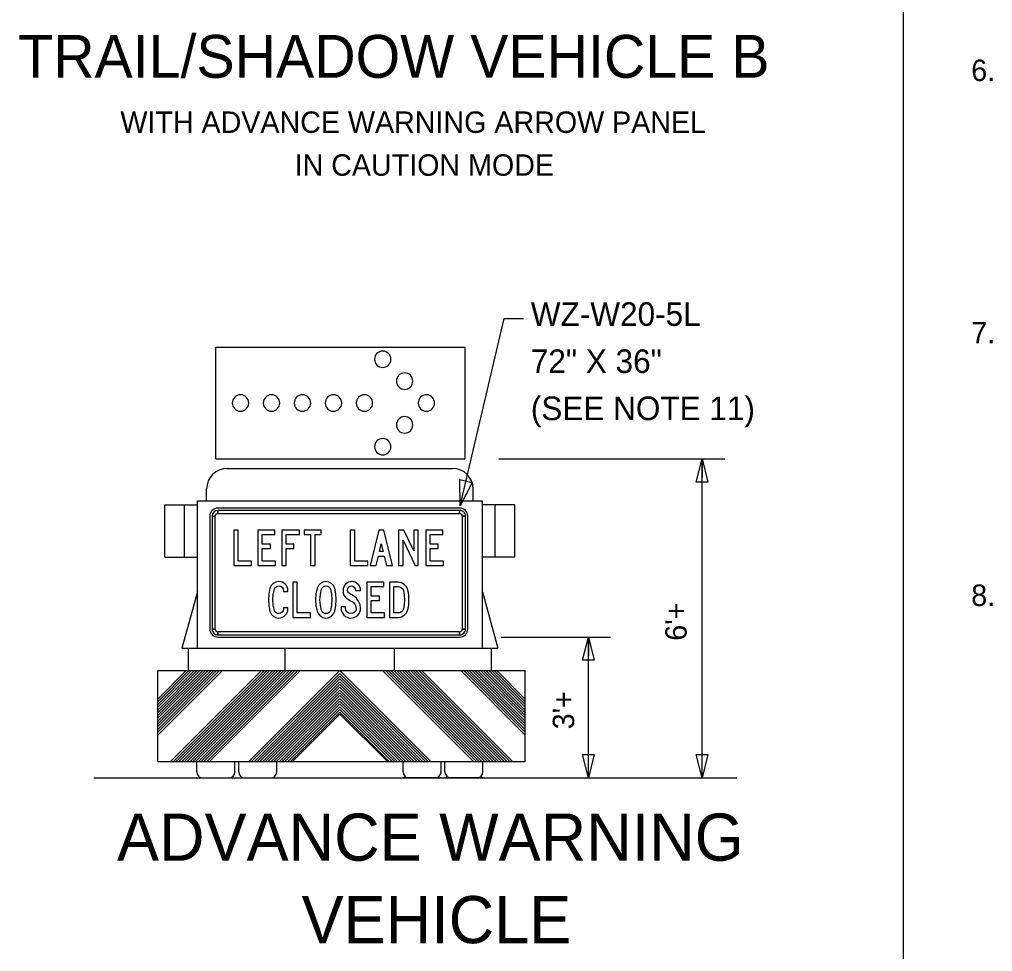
# Model space of a CAD drawing. Extents: x -747 to 834, y -5485 to -3577.
# Drawn here: x 69.1 to 341.6, y -5217.7 to -4956.7 of the extents above; entities that cross this region are included whole.
import ezdxf

# ---------------------------------------------------------------- set-up
doc = ezdxf.new("R2010")
doc.units = 0
doc.layers.add('Working Level 1', color=7, linetype='Continuous')

msp = doc.modelspace()

# ---------------------------------------------------------------- linework, layer by layer
at = {"layer": 'Working Level 1'}
for p, q in [((316.57, -4442.19), (316.57, -5484.51)), ((124.09, -5048.46), (193.86, -5048.46)), ((124.09, -5079.75), (124.09, -5048.46)), ((193.86, -5079.75), (193.86, -5048.46)), ((124.09, -5079.75), (193.86, -5079.75)), ((203.33, -5079.75), (266.6, -5079.75)), ((260.24, -5169.06), (260.24, -5079.75)), ((260.24, -5079.75), (260.24, -5084.99)), ((127.24, -5082.43), (190.38, -5082.43)), ((121.49, -5091.46), (121.49, -5088.16)), ((196.12, -5091.46), (196.12, -5088.16)), ((109.78, -5092.62), (118.89, -5092.62)), ((109.78, -5107.29), (109.78, -5092.62)), ((115.3, -5107.29), (115.3, -5092.62)), ((118.89, -5132.72), (118.89, -5091.46)), ((118.89, -5091.46), (198.72, -5091.46)), ((192.35, -5093.53), (124.64, -5093.53)), ((198.72, -5132.72), (198.72, -5091.46)), ((207.83, -5092.62), (198.72, -5092.62)), ((202.31, -5107.29), (202.31, -5092.62)), ((207.83, -5107.29), (207.83, -5092.62)), ((122.38, -5095.78), (122.38, -5127.38)), ((123.01, -5095.78), (123.88, -5095.78)), ((124.64, -5095.03), (124.64, -5094.15)), ((192.35, -5094.15), (192.35, -5095.03)), ((193.1, -5095.78), (193.98, -5095.78)), ((194.61, -5127.38), (194.61, -5095.78)), ((109.78, -5107.29), (118.89, -5107.29)), ((207.83, -5107.29), (198.72, -5107.29)), ((118.89, -5117), (114.58, -5132.72)), ((198.72, -5117), (203.04, -5132.72)), ((123.88, -5127.38), (123.01, -5127.38)), ((124.64, -5129.01), (124.64, -5128.14)), ((192.35, -5128.14), (192.35, -5129.01)), ((193.98, -5127.38), (193.1, -5127.38)), ((124.64, -5129.64), (192.35, -5129.64)), ((203.98, -5129.64), (234.6, -5129.64)), ((228.43, -5169.06), (228.43, -5129.64)), ((228.43, -5129.64), (228.43, -5134.97)), ((114.58, -5132.72), (203.04, -5132.72)), ((116.37, -5139.03), (116.37, -5132.72)), ((143.49, -5139.03), (143.49, -5132.84)), ((174.12, -5139.03), (174.12, -5132.84)), ((201.24, -5139.03), (201.24, -5132.72)), ((107.8, -5139.03), (210.75, -5139.03)), ((107.8, -5139.03), (210.75, -5139.03)), ((107.8, -5139.03), (210.75, -5139.03)), ((107.8, -5139.03), (210.75, -5139.03)), ((107.8, -5164.52), (107.8, -5139.03)), ((107.8, -5147.01), (115.78, -5139.03)), ((107.8, -5156.28), (125.06, -5139.03)), ((107.8, -5155.5), (124.28, -5139.03)), ((107.8, -5154.72), (123.5, -5139.03)), ((107.8, -5153.95), (122.73, -5139.03)), ((107.8, -5153.17), (121.95, -5139.03)), ((107.8, -5152.39), (121.16, -5139.03)), ((107.8, -5151.62), (120.39, -5139.03)), ((107.8, -5150.84), (119.61, -5139.03)), ((107.8, -5150.06), (118.83, -5139.03)), ((107.8, -5149.28), (118.05, -5139.03)), ((107.8, -5148.51), (117.28, -5139.03)), ((107.8, -5147.73), (116.5, -5139.03)), ((107.8, -5157.06), (125.81, -5139.05)), ((111.39, -5164.52), (136.89, -5139.03)), ((112.17, -5164.52), (137.66, -5139.03)), ((112.95, -5164.52), (138.45, -5139.03)), ((113.73, -5164.52), (139.23, -5139.03)), ((114.5, -5164.52), (140, -5139.03)), ((115.28, -5164.52), (140.78, -5139.03)), ((116.06, -5164.52), (141.56, -5139.03)), ((116.84, -5164.52), (142.34, -5139.03)), ((117.61, -5164.52), (143.11, -5139.03)), ((118.39, -5164.52), (143.89, -5139.03)), ((119.17, -5164.52), (144.67, -5139.03)), ((119.94, -5164.52), (145.44, -5139.03)), ((120.72, -5164.52), (146.22, -5139.03)), ((121.51, -5164.52), (146.99, -5139.04)), ((122.28, -5164.52), (147.78, -5139.03)), ((133.31, -5164.52), (158.81, -5139.03)), ((134.08, -5164.52), (158.81, -5139.8)), ((184.3, -5164.52), (158.81, -5139.03)), ((183.49, -5164.48), (158.81, -5139.8)), ((196.27, -5164.52), (170.77, -5139.03)), ((197.04, -5164.52), (171.56, -5139.04)), ((197.82, -5164.52), (172.33, -5139.03)), ((198.6, -5164.52), (173.11, -5139.03)), ((199.37, -5164.52), (173.88, -5139.03)), ((200.16, -5164.52), (174.66, -5139.03)), ((200.94, -5164.52), (175.44, -5139.03)), ((201.71, -5164.52), (176.21, -5139.03)), ((202.49, -5164.52), (176.99, -5139.03)), ((203.27, -5164.52), (177.77, -5139.03)), ((204.05, -5164.52), (178.55, -5139.03)), ((204.82, -5164.52), (179.32, -5139.03)), ((205.6, -5164.52), (180.1, -5139.03)), ((206.38, -5164.52), (180.88, -5139.03)), ((207.16, -5164.52), (181.66, -5139.03)), ((210.75, -5157.06), (192.74, -5139.05)), ((210.75, -5156.28), (193.49, -5139.03)), ((210.75, -5155.5), (194.27, -5139.03)), ((210.75, -5154.72), (195.05, -5139.03)), ((210.75, -5153.95), (195.82, -5139.03)), ((210.75, -5153.17), (196.6, -5139.03)), ((210.75, -5152.39), (197.38, -5139.03)), ((210.75, -5151.62), (198.15, -5139.03)), ((210.75, -5150.84), (198.93, -5139.03)), ((210.75, -5150.06), (199.72, -5139.03)), ((210.75, -5149.28), (200.5, -5139.03)), ((210.75, -5148.51), (201.27, -5139.03)), ((210.75, -5147.73), (202.05, -5139.03)), ((210.75, -5147.01), (202.77, -5139.03)), ((210.75, -5164.52), (210.75, -5139.03)), ((134.86, -5164.52), (158.81, -5140.58)), ((135.65, -5164.52), (158.81, -5141.36)), ((136.42, -5164.52), (158.81, -5142.13)), ((137.2, -5164.52), (158.81, -5142.91)), ((182.75, -5164.52), (158.81, -5140.58)), ((181.97, -5164.52), (158.81, -5141.36)), ((181.2, -5164.52), (158.81, -5142.13)), ((180.42, -5164.52), (158.81, -5142.91)), ((137.98, -5164.52), (158.81, -5143.7)), ((138.75, -5164.52), (158.81, -5144.47)), ((139.53, -5164.52), (158.81, -5145.25)), ((179.64, -5164.52), (158.81, -5143.7)), ((178.87, -5164.52), (158.81, -5144.47)), ((178.09, -5164.52), (158.81, -5145.25)), ((140.31, -5164.52), (158.81, -5146.03)), ((141.09, -5164.52), (158.81, -5146.81)), ((141.86, -5164.52), (158.81, -5147.58)), ((142.64, -5164.52), (158.81, -5148.36)), ((177.31, -5164.52), (158.81, -5146.03)), ((176.53, -5164.52), (158.81, -5146.81)), ((175.76, -5164.52), (158.81, -5147.58)), ((174.98, -5164.52), (158.81, -5148.36)), ((143.42, -5164.52), (158.81, -5149.14)), ((144.19, -5164.52), (158.81, -5149.91)), ((144.97, -5164.52), (158.81, -5150.69)), ((145.62, -5164.38), (158.81, -5151.19)), ((174.2, -5164.52), (158.81, -5149.14)), ((173.43, -5164.52), (158.81, -5149.91)), ((172.64, -5164.52), (158.81, -5150.69)), ((172.14, -5164.52), (158.81, -5151.19)), ((107.8, -5164.52), (210.75, -5164.52)), ((107.8, -5164.52), (210.75, -5164.52)), ((107.8, -5164.52), (210.75, -5164.52)), ((107.8, -5164.52), (210.75, -5164.52)), ((118.74, -5167.41), (118.74, -5164.52)), ((129.38, -5167.41), (129.38, -5164.52)), ((130.48, -5167.41), (130.48, -5164.52)), ((141.11, -5167.41), (141.11, -5164.52)), ((176.5, -5167.41), (176.5, -5164.52)), ((187.14, -5167.41), (187.14, -5164.52)), ((188.24, -5167.41), (188.24, -5164.52)), ((198.87, -5167.41), (198.87, -5164.52)), ((89.92, -5169.06), (270.03, -5169.06)), ((118.74, -5169.06), (129.38, -5169.06)), ((118.74, -5169.06), (129.38, -5169.06)), ((118.74, -5169.06), (129.38, -5169.06)), ((118.74, -5169.06), (129.38, -5169.06)), ((130.48, -5169.06), (141.11, -5169.06)), ((130.48, -5169.06), (141.11, -5169.06)), ((130.48, -5169.06), (141.11, -5169.06)), ((130.48, -5169.06), (141.11, -5169.06)), ((187.14, -5169.06), (176.5, -5169.06)), ((187.14, -5169.06), (176.5, -5169.06)), ((187.14, -5169.06), (176.5, -5169.06)), ((187.14, -5169.06), (176.5, -5169.06)), ((198.87, -5169.06), (188.24, -5169.06)), ((198.87, -5169.06), (188.24, -5169.06)), ((198.87, -5169.06), (188.24, -5169.06)), ((198.87, -5169.06), (188.24, -5169.06))]:
    msp.add_line(p, q, dxfattribs=at)
for points in [[(192.5, -5092.87), (204.84, -5040.47), (210.24, -5040.47)], [(173.51, -5109.58), (171.11, -5099.72), (169.71, -5099.72), (167.3, -5109.58), (168.93, -5109.58), (169.58, -5106.94), (171.23, -5106.94), (171.88, -5109.58), (173.51, -5109.58)], [(170.94, -5105.71), (169.88, -5105.71), (170.41, -5103.54), (170.94, -5105.71)], [(157.81, -5119.19), (157.7, -5117.54), (157.37, -5115.93), (157.03, -5115.2), (156.47, -5114.61), (155.73, -5114.22), (154.91, -5114.09), (154.08, -5114.22), (153.35, -5114.61), (152.78, -5115.21), (152.44, -5115.94), (152.11, -5117.55), (152.01, -5119.19), (152.11, -5120.82), (152.44, -5122.43), (152.78, -5123.17), (153.35, -5123.77), (154.08, -5124.17), (154.91, -5124.3), (155.74, -5124.17), (156.48, -5123.77), (157.04, -5123.17), (157.38, -5122.42), (157.7, -5120.82), (157.81, -5119.19)], [(156.58, -5119.2), (156.47, -5120.71), (156.15, -5122.2), (155.98, -5122.55), (155.69, -5122.83), (155.32, -5123.01), (154.91, -5123.07), (154.49, -5123.01), (154.12, -5122.82), (153.83, -5122.54), (153.67, -5122.19), (153.34, -5120.71), (153.24, -5119.2), (153.34, -5117.68), (153.67, -5116.19), (153.83, -5115.84), (154.12, -5115.57), (154.49, -5115.39), (154.91, -5115.33), (155.32, -5115.39), (155.69, -5115.57), (155.98, -5115.84), (156.15, -5116.18), (156.47, -5117.67), (156.58, -5119.2)], [(172.71, -5124.12), (175.11, -5124.12), (176.04, -5123.97), (176.86, -5123.52), (177.49, -5122.83), (177.84, -5121.98), (178.08, -5120.61), (178.16, -5119.2), (178.08, -5117.79), (177.84, -5116.41), (177.49, -5115.56), (176.86, -5114.88), (176.04, -5114.42), (175.11, -5114.27), (172.71, -5114.27), (172.71, -5124.12)], [(173.94, -5122.89), (173.94, -5115.5), (175.14, -5115.5), (175.64, -5115.58), (176.09, -5115.81), (176.43, -5116.17), (176.63, -5116.61), (176.85, -5117.89), (176.93, -5119.2), (176.85, -5120.51), (176.63, -5121.78), (176.43, -5122.22), (176.09, -5122.58), (175.64, -5122.82), (175.14, -5122.89), (173.94, -5122.89)]]:
    msp.add_lwpolyline(points, dxfattribs=at)
for points in [[(258.61, -5086.25), (260.24, -5079.75), (261.86, -5086.25)], [(195.88, -5086.32), (192.5, -5092.87), (192.4, -5085.5)], [(123.01, -5095.78), (123.01, -5127.38), (123.88, -5127.38), (123.88, -5095.78), (123.01, -5095.78)], [(192.35, -5094.15), (124.64, -5094.15), (124.64, -5095.03), (192.35, -5095.03), (192.35, -5094.15)], [(193.98, -5127.38), (193.98, -5095.78), (193.1, -5095.78), (193.1, -5127.38), (193.98, -5127.38)], [(134.07, -5109.58), (134.07, -5108.35), (130.34, -5108.35), (130.34, -5099.72), (129.11, -5099.72), (129.11, -5109.58)], [(140.78, -5109.58), (140.78, -5108.35), (137.05, -5108.35), (137.05, -5104.83), (139.34, -5104.83), (139.34, -5103.59), (137.05, -5103.59), (137.05, -5100.95), (140.62, -5100.95), (140.62, -5099.72), (135.82, -5099.72), (135.82, -5109.58)], [(147.49, -5100.95), (147.49, -5099.72), (142.53, -5099.72), (142.53, -5109.58), (143.76, -5109.58), (143.76, -5104.83), (145.87, -5104.83), (145.87, -5103.59), (143.76, -5103.59), (143.76, -5100.95)], [(153.61, -5100.95), (153.61, -5099.72), (148.85, -5099.72), (148.85, -5100.95), (150.61, -5100.95), (150.61, -5109.58), (151.85, -5109.58), (151.85, -5100.95)], [(166.68, -5109.58), (166.68, -5108.35), (162.95, -5108.35), (162.95, -5099.72), (161.72, -5099.72), (161.72, -5109.58)], [(180.72, -5109.58), (180.72, -5099.72), (179.49, -5099.72), (179.49, -5105.47), (176.7, -5099.72), (175.27, -5099.72), (175.27, -5109.58), (176.5, -5109.58), (176.5, -5102.53), (179.93, -5109.58)], [(187.83, -5109.58), (187.83, -5108.35), (184.1, -5108.35), (184.1, -5104.83), (186.38, -5104.83), (186.38, -5103.59), (184.1, -5103.59), (184.1, -5100.95), (187.67, -5100.95), (187.67, -5099.72), (182.87, -5099.72), (182.87, -5109.58)], [(144.25, -5121.48), (143.02, -5121.48), (143.02, -5121.76), (142.92, -5122.26), (142.63, -5122.69), (142.21, -5122.97), (141.71, -5123.07), (141.29, -5123.01), (140.92, -5122.82), (140.62, -5122.54), (140.45, -5122.19), (140.13, -5120.71), (140.03, -5119.2), (140.13, -5117.69), (140.45, -5116.21), (140.62, -5115.86), (140.92, -5115.57), (141.29, -5115.39), (141.71, -5115.33), (142.21, -5115.42), (142.63, -5115.71), (142.92, -5116.13), (143.02, -5116.63), (143.02, -5116.91), (144.25, -5116.91), (144.25, -5116.66), (144.2, -5116.15), (144.06, -5115.68), (143.83, -5115.24), (143.5, -5114.85), (143.11, -5114.52), (142.67, -5114.28), (142.2, -5114.14), (141.69, -5114.09), (140.86, -5114.23), (140.12, -5114.62), (139.56, -5115.23), (139.21, -5115.97), (138.9, -5117.58), (138.79, -5119.19), (138.9, -5120.84), (139.22, -5122.43), (139.56, -5123.18), (140.13, -5123.77), (140.86, -5124.17), (141.69, -5124.3), (142.2, -5124.25), (142.67, -5124.11), (143.11, -5123.88), (143.5, -5123.55), (143.83, -5123.15), (144.06, -5122.72), (144.2, -5122.25), (144.25, -5121.73)], [(150.6, -5124.12), (150.6, -5122.89), (146.87, -5122.89), (146.87, -5114.27), (145.64, -5114.27), (145.64, -5124.12)], [(159.16, -5121.13), (159.16, -5121.54), (159.21, -5122.09), (159.36, -5122.6), (159.61, -5123.07), (159.96, -5123.49), (160.38, -5123.85), (160.84, -5124.1), (161.34, -5124.25), (161.88, -5124.3), (162.43, -5124.25), (162.94, -5124.1), (163.4, -5123.85), (163.82, -5123.5), (164.17, -5123.08), (164.42, -5122.62), (164.56, -5122.12), (164.62, -5121.57), (164.48, -5120.52), (164.06, -5119.55), (163.43, -5118.73), (162.62, -5118.1), (161.54, -5117.43), (161.07, -5117.02), (160.92, -5116.45), (161, -5116.02), (161.25, -5115.66), (161.61, -5115.41), (162.04, -5115.33), (162.47, -5115.42), (162.83, -5115.69), (163.08, -5116.09), (163.16, -5116.56), (164.62, -5116.56), (164.57, -5116.07), (164.43, -5115.61), (164.21, -5115.2), (163.89, -5114.82), (163.51, -5114.5), (163.09, -5114.27), (162.64, -5114.14), (162.15, -5114.09), (161.65, -5114.14), (161.2, -5114.28), (160.78, -5114.51), (160.41, -5114.84), (160.09, -5115.23), (159.87, -5115.65), (159.73, -5116.12), (159.69, -5116.63), (159.75, -5117.31), (159.95, -5117.9), (160.27, -5118.4), (160.73, -5118.81), (161.81, -5119.46), (162.5, -5119.9), (162.99, -5120.42), (163.29, -5121.04), (163.38, -5121.74), (163.27, -5122.25), (162.94, -5122.68), (162.46, -5122.97), (161.88, -5123.07), (161.31, -5122.96), (160.83, -5122.63), (160.5, -5122.15), (160.39, -5121.57), (160.39, -5121.13)], [(171.3, -5124.12), (171.3, -5122.89), (167.57, -5122.89), (167.57, -5119.37), (169.86, -5119.37), (169.86, -5118.14), (167.57, -5118.14), (167.57, -5115.5), (171.14, -5115.5), (171.14, -5114.27), (166.34, -5114.27), (166.34, -5124.12)], [(124.64, -5129.01), (192.35, -5129.01), (192.35, -5128.14), (124.64, -5128.14), (124.64, -5129.01)], [(226.8, -5136.14), (228.43, -5129.64), (230.05, -5136.14)], [(230.05, -5162.56), (228.43, -5169.06), (226.8, -5162.56)], [(261.86, -5162.56), (260.24, -5169.06), (258.61, -5162.56)]]:
    msp.add_lwpolyline(points, close=True, dxfattribs=at)
for centre, radius, start, end in [((170.81, -5051.84), 2.3, 0, 180), ((170.81, -5051.84), 2.3, 180, 0), ((176.93, -5057.97), 2.3, 0, 180), ((176.93, -5057.97), 2.3, 180, 0), ((130.97, -5064.1), 2.3, 0, 180), ((139.65, -5064.1), 2.3, 0, 180), ((148.33, -5064.1), 2.3, 0, 180), ((157.01, -5064.1), 2.3, 0, 180), ((165.69, -5064.1), 2.3, 0, 180), ((183.05, -5064.1), 2.3, 0, 180), ((130.97, -5064.1), 2.3, 180, 0), ((139.65, -5064.1), 2.3, 180, 0), ((148.33, -5064.1), 2.3, 180, 0), ((157.01, -5064.1), 2.3, 180, 0), ((165.69, -5064.1), 2.3, 180, 0), ((183.05, -5064.1), 2.3, 180, 0), ((176.93, -5070.22), 2.3, 0, 180), ((176.93, -5070.22), 2.3, 180, 0), ((170.81, -5076.34), 2.3, 0, 180), ((170.81, -5076.34), 2.3, 180, 0), ((127.23, -5088.16), 5.74, 90, 180), ((190.38, -5088.16), 5.74, 0, 90), ((124.64, -5095.78), 2.26, 90.0002, 179.9998), ((192.35, -5095.78), 2.26, 0, 90.0002), ((124.64, -5095.78), 1.63, 90.0002, 179.9998), ((124.64, -5095.78), 0.752, 90.0002, 179.9998), ((192.35, -5095.78), 1.63, 0, 90.0002), ((192.35, -5095.78), 0.752, 0, 90.0002), ((124.64, -5127.38), 2.26, 179.9998, 270.0001), ((124.64, -5127.38), 1.63, 179.9998, 270.0001), ((124.64, -5127.38), 0.752, 179.9998, 270.0001), ((192.35, -5127.38), 2.26, 270.0001, 0.0003), ((192.35, -5127.38), 1.63, 270.0001, 0.0003), ((192.35, -5127.38), 0.752, 270.0001, 0.0003), ((120.39, -5167.41), 1.65, 180, 270), ((127.73, -5167.41), 1.65, 270, 0), ((132.13, -5167.41), 1.65, 180, 270), ((139.46, -5167.41), 1.65, 270, 0), ((178.15, -5167.41), 1.65, 180, 270), ((185.49, -5167.41), 1.65, 270, 0), ((189.89, -5167.41), 1.65, 180, 270), ((197.22, -5167.41), 1.65, 270, 0)]:
    msp.add_arc(centre, radius, start, end, dxfattribs=at)

# ---------------------------------------------------------------- texts
for s, height, p in [('TRAIL/SHADOW VEHICLE B', 12, (68.7, -4973.02)), ('6. ', 6, (335.65, -4973.93)), ('WITH ADVANCE WARNING ARROW PANEL', 6, (97.33, -4988.46)), ('IN CAUTION MODE', 6, (146.13, -5000.46)), ('WZ-W20-5L', 6.6, (212.29, -5042.49)), ('7. ', 6, (335.65, -5047.43)), ('72" X 36"', 6.6, (212.29, -5055.69)), ('(SEE NOTE 11)', 6.6, (212.29, -5068.89)), ('8.', 6, (335.65, -5120.93)), ('ADVANCE WARNING', 13.2, (96.38, -5192.26)), ('VEHICLE ', 13.2, (148.09, -5215.36))]:
    msp.add_text(s, height=height, dxfattribs=at).set_placement(p)
for s, p in [("6'+", (255.94, -5130.66)), ("3'+", (224.44, -5155.47))]:
    msp.add_text(s, height=6, rotation=90, dxfattribs=at).set_placement(p)

doc.saveas('drawing.dxf')
